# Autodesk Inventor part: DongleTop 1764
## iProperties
Created: 2010-01
Part Number: DongleTop 1764
Document SubType Name: Modeling
Designer: jgehrig
Density: 1 g/cm^3
Author: jgehrig
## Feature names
1. Extrusion1
2. Fillet1
3. Shell1
4. Fillet2
5. Extrusion2
6. Extrusion3
7. Extrusion4
